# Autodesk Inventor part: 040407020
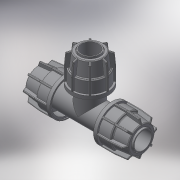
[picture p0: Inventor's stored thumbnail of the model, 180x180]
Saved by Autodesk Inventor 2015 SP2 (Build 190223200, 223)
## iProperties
Created: 2017-08
Part Number: 040407020
Material: Generic
Description: PLASSON IRRIFIT TEE 20-20-20
Document SubType Name: Modeling
Designer: KIM
Density: 1 g/cm^3
Appearance: Default
Author: KIM
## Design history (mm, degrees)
derived "040407.ipt"
feature "Solid1::040407.ipt"
tag "TaggingFeature1"
body "Solid1"
other parameters: "d5" = 34.2, "d6" = 17.1, "d10" = 39, "d22" = 28, "d24" = 3.8, "d25" = 35.1, "d26" = 31.2, "d31" = 1, "d49" = 1.95, "d50" = 0, "d58" = 0.6, "d61" = 360 deg, "d78" = 6 deg, "d80" = 22, "d81" = 55, "d82" = 2.85, "d84" = 5 deg, "d85" = 70 deg, "d86" = 37.05, "d87" = 0.95, "d88" = 0, "d89" = 33.15, "d90" = 9.5, "d91" = 0, "d93" = 180 deg, "d96" = 0, "d98" = 0, "E_" = 39, "l_" = 19
